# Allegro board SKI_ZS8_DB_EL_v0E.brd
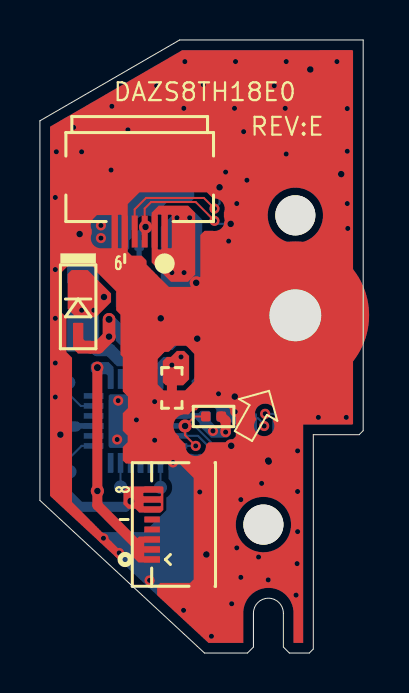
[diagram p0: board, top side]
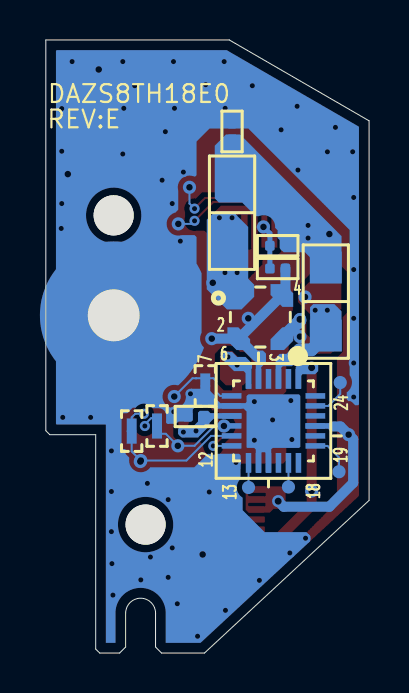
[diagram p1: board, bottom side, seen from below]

Outline 16.2 x 30.66 mm; copper layers: TOP, SGND, IN1, IN2, SVCC, IN3, SGND1, BOTTOM. Coordinates in mm from the lower left corner of the outline.
Outline path: 0,26.62 7,30.66 16.2,30.66 16.2,11.12 16,10.92 13.7,10.92 13.7,0.2 13.5,0 12.5,0 12.2,0.3 12.2,2 arc(11.45,2.75) 10.7,2 10.7,0.3 10.4,0 8.25,0 0,7.63 0,26.62

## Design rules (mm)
net group W20-T123B: nets +5V COM CS EL1 LX MAX14521E_1

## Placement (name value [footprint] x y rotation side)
C1  0.1u/25v_4  [CC0402]  8.7 11.83 0 bottom
C5  330p/50v_4  [CC0402]  4.58 20.37 180 bottom
C6  3300p/250v_1206  [CC1206]  2.17 17.58 90 bottom
CN1  196033-06021-3  [AF706L-A2G1T-6P-L-SMT]  5 23.88 180 top
CN2  50696-00801-001  [50696-0080M-V02-8P-L]  8.12 6.43 90 top
D4  bav21ws-7-f  [DSM]  1.91 17.32 270 top
HOLE1  *h-c291ic142d102p2  [H-C291IC142D102P2]  12.8 16.89 0 top
HOLE4  *h-c79d79n  [H-C79D79N]  12.8 21.89 0 top
HOLE5  *h-c79d79n  [H-C79D79N]  11.2 6.42 0 top
L10  mlps-3014pf-1r9111 /0.7a  [L3X3-1_4-4P]  5.45 16.8 180 bottom
NOREF  -  []  14.28 -45.03 0 top
NOREF#2  -  []  -39.05 -85.23 0 top
PC160  10u/25v_1206  [CC1206]  6.87 22.02 270 bottom
R20  *short_4  [SHORT0402]  10.63 11.35 270 bottom
R21  *short_4  [SHORT0402]  11.9 11.1 270 bottom
R24  20_4  [RC0402]  4.58 19.23 0 bottom
R25  *short_4  [SHORT0402]  8.21 13.35 90 bottom
R39  33k/f_4  [RC0402]  8.7 11.83 0 top
R40  *short_4  [SHORT0402]  6.61 13.26 270 top
R41  *0_4  [RC0402]  6.87 26.09 270 bottom
TP13  *pad  [TP2675]  6.04 8.28 180 bottom
TP15  *pad  [TP2675]  1.45 13.53 180 bottom
TP16  *pad  [TP2675]  1.51 9.07 180 bottom
TP17  *pad  [TP2675]  4.04 8.31 180 bottom
U1  max14521e  [QFN24-4X4-5-25P]  4.79 11.61 270 bottom

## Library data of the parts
C1 C5 = CC0402
C6 PC160 = CC1206
CN1 = AF706L-A2G1T-6P-L-SMT
CN2 = 50696-0080M-V02-8P-L
D4 = DSM
HOLE1 = H-C291IC142D102P2
HOLE4 HOLE5 = H-C79D79N
L10 = L3X3-1_4-4P
R20 R21 R25 R40 = SHORT0402
R24 R39 R41 = RC0402
TP13 TP15-TP17 = TP2675
U1 = QFN24-4X4-5-25P

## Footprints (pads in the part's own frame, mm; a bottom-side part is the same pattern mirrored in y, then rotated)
50696-0080M-V02-8P-L
  rect 0.305x0.787 smd: 1(-1.75,2.5) 2(-1.25,2.5) 3(-0.75,2.5) 4(-0.25,2.5) 5(0.25,2.5) 6(0.75,2.5) 7(1.25,2.5) 8(1.75,2.5)
  rect 0.406x0.787 smd: 9(-2.75,0) 10(2.75,0)
AF706L-A2G1T-6P-L-SMT
  rect 0.305x1.6 smd: 1(-1.25,2.8) 2(-0.75,2.8) 3(-0.25,2.8) 4(0.25,2.8) 5(0.75,2.8) 6(1.25,2.8)
  rect 1.803x1.397 smd: 7(-2.9,0) 8(2.9,0)
CC0402
  custom 0.12x0.12 smd: 1(0.39,0) 2(-0.39,0)
CC1206
  rect 1.6x1.6 smd: 1(1.702,0) 2(-1.702,0)
DSM
  rect 1.016x0.508 smd: 1(-1.3,0) 2(1.321,0)
H-C79D79N
  round 2.007 hole 2.007 unplated: (0,0)
H-C291IC142D102P2
  round 7.391 hole 2.591: 1(0,0)
L3X3-1_4-4P
  custom 0.285x0.285 smd: 1(-1.08,1.08) 2(-1.08,-1.08) 3(1.08,-1.08) 4(1.08,1.08)
QFN24-4X4-5-25P
  rect 0.991x0.279 smd: 1(-2.1,1.25) 2(-2.1,0.75) 3(-2.1,0.25) 4(-2.1,-0.25) 5(-2.1,-0.75) 6(-2.1,-1.25) 13(2.1,-1.25) 14(2.1,-0.75) 15(2.1,-0.25) 16(2.1,0.25) 17(2.1,0.75) 18(2.1,1.25)
  rect 0.279x0.991 smd: 7(-1.25,-2.1) 8(-0.75,-2.1) 9(-0.25,-2.1) 10(0.25,-2.1) 11(0.75,-2.1) 12(1.25,-2.1) 19(1.25,2.1) 20(0.75,2.1) 21(0.25,2.1) 22(-0.25,2.1) 23(-0.75,2.1) 24(-1.25,2.1)
  rect 2.591x2.591 smd: 25(0,0)
RC0402
  custom 0.12x0.12 smd: 1(0.39,0) 2(-0.39,0)
SHORT0402
  rect 0.648x0.5 smd: 1(-0.39,0) 2(0.39,0)
TP2675
  round 0.66 smd: 1(0,0)

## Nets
+5V: C1.2 CN1.1 CN1.2 L10.1 PC160.1 R39.1 U1.9
GND: C1.1 CN1.5 CN1.6 CN1.7 CN1.8 CN2.9 CN2.10 HOLE1.1 R25.1 R40.2 R41.2 U1.8 U1.14 U1.15 U1.25
PGND: C5.1 C6.1 PC160.2 R40.1 R41.1 U1.6
AUX: TP13.1 U1.13
COM: CN2.6 CN2.7 CN2.8 U1.21
CS: C6.2 D4.1 U1.3
EL1: CN2.1 CN2.2 CN2.3 U1.1
EL2: TP15.1 U1.23
EL3: TP16.1 U1.19
EL4: TP17.1 U1.17
EL_SCL: CN1.4 R21.1
EL_SDA: CN1.3 R20.1
KEYBOARD_SCL: R21.2 U1.11
KEYBOARD_SDA: R20.2 U1.10
LX: L10.2 L10.4 R24.2 U1.5
MAX14521E_1: D4.2 L10.3
RB: R39.2 U1.12
N17530158: C5.2 R24.1
N17530494: R25.2 U1.7

Pads without a net: CN2 4 5; U1 2 4 16 18 20 22 24

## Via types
v1: diameter 0.66, hole 0.33, TOP to BOTTOM, 19 vias
v2: diameter 0.61, hole 0.356, TOP to BOTTOM, 3 vias
v3: diameter 0.508, hole 0.254, TOP to BOTTOM, 76 vias

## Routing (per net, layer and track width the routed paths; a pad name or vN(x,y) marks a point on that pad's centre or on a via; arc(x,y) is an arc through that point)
+5V: length 0.9
  TOP w0.508: v3(9.31,11.05) 9.31,11.62 R39.1
  vias: v1(7.83,18.52) v3(6.61,19.02) v3(6.87,21.77) v3(7.22,19.02) v3(7.5,21.77) v3(8.67,11.11)
GND:
  vias: v1(6.06,16.74) v1(8.34,4.93) v1(11.47,9.58) v1(13.55,29.18) v1(15.1,23.95) v3(0.82,25.07) v3(0.77,22.78) v3(0.77,19.18) v3(0.77,16.74) v3(0.77,14.5) v3(0.77,12.8) v3(1.69,26.29) v3(2.09,25.07) v3(3.18,5.74) v3(3.61,27.34) v3(3.57,24.16) v3(3.92,12.62) v3(3.87,10.68) v3(3.97,5) v3(4.41,26.17) v3(4.84,11.66) v3(5.5,3.63) v3(5.75,12.57) v3(5.75,10.64) v3(5.85,28.37) v3(6.67,9.53) v3(7.21,27.24) v3(7.2,2.13) v3(7.26,29.58) v3(8.01,8.05) v3(8.19,28.42) v3(8.6,0.84) v3(8.95,12.96) v3(9.31,24.05) v3(9.46,20.6) v3(9.61,2.46) v3(9.8,29.58) v3(9.75,27.24) v3(9.79,12.07) v3(9.87,22.48) v3(9.87,5.26) v3(10.07,7.67) v3(10.07,3.78) v3(10.21,26.07) v3(10.37,23.65) v3(10.96,4.8) v3(11.11,8.48) v3(11.44,3.66) v3(11.74,28.37) v3(12.34,29.58) v3(12.29,27.24) v3(12.34,24.96) v3(12.84,2.9) v3(12.91,10.11) v3(12.91,8.08) v3(12.91,6.07) v3(12.89,4.47) v3(13.95,11.79) v3(14.88,29.58) v3(15.4,27.23) v3(15.4,25.1) v3(15.4,22.48) v3(15.43,21.23) v3(15.35,11.79)
PGND:
  vias: v1(1.99,20.95) v3(3.06,21.39) v3(3.06,20.75) v3(6.61,14.4) v3(7.07,14.81)
AUX: length 1.2
  BOTTOM w0.102: TP13.1 U1.13
COM: length 7.8
  BOTTOM w0.508: v2(4.56,7.59) 4.28,7.32 1.99,7.32 0.8,8.51 0.8,10.69 v1(1.03,10.92) 1.43,11.33 1.81,11.33
CS: length 2.2
  BOTTOM w0.635: 3.92,14.73 3.49,15.16 2.88,15.16 C6.2
  vias: v1(3.21,17.81) v3(2.09,17.15) v3(2.7,17.15)
EL1: length 9.8
  TOP w0.508: v2(2.88,14.27) v1(2.88,8.1) 2.88,7.39 4.91,5.36
EL2: length 2.1
  BOTTOM w0.102: U1.23 2.04,12.36 1.45,12.95 TP15.1
EL3: length 2.1
  BOTTOM w0.102: TP16.1 1.51,9.78 2.09,10.36 U1.19
EL4: length 1.2
  BOTTOM w0.102: TP17.1 U1.17
EL_SCL: length 19.3
  TOP w0.102: CN1.4 4.75,22.19 5.32,22.76 8.21,22.76 v3(8.75,22.23)
  IN1 w0.114: v3(11.29,11.96) 8.9,14.35 8.9,21.01 9.2,21.31 9.2,21.77 v3(8.75,22.23)
  BOTTOM w0.102: v3(11.29,11.96) 11.72,11.96 11.9,11.79 R21.1 ; v1(9,23.29) 9,22.48 v3(8.75,22.23)
EL_SDA: length 18.2
  TOP w0.102: v3(8.75,21.62) 7.81,22.56 5.57,22.56 5.25,22.23 CN1.3
  IN1 w0.114: v3(8.75,21.62) 8.65,21.51 8.65,13.94 v3(11.24,11.35)
  BOTTOM w0.102: v3(8.75,21.62) 8.9,21.46 v1(9.56,21.46) ; v3(11.24,11.35) 11.24,11.43 10.92,11.74 R20.1
KEYBOARD_SCL: length 6.3
  BOTTOM w0.102: R21.2 11.9,10.08 v1(11.44,9.63) 9.15,9.63 7.92,10.86 U1.11
KEYBOARD_SDA: length 4.4
  BOTTOM w0.102: U1.10 7.75,11.36 8.75,10.36 v1(9.59,10.36) 10.19,10.96 R20.2
LX: length 7.1
  BOTTOM w0.508: R24.2 4.19,18.06 L10.4 L10.2 ; 5.63,14.82 L10.2 ; L10.2 v1(7.88,15.72)
MAX14521E_1: length 3.3
  TOP w0.635: v2(3.46,16.69) v1(3.46,15.82) 2.93,15.29 2.55,15.29
  BOTTOM w0.635: v2(3.46,16.69) 3.46,16.63 L10.3
RB: length 3.4
  TOP w0.102: v3(7.81,10.36) 7.27,10.89 v1(7.27,11.35) 7.75,11.83 R39.2
  BOTTOM w0.102: v3(7.81,10.36) U1.12
N17530158: length 2.2
  BOTTOM w0.254: R24.1 C5.2 4.97,20.99 v1(5.29,21.31)
N17530494: length 3.9
  BOTTOM w0.102: v1(9.76,12.83) 8.85,13.74 8.67,13.74 8.67,13.74 R25.2 7.81,13.74 7.66,13.59 7.66,13.06 7.46,12.86 U1.7

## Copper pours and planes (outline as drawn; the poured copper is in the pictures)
+5V on TOP (solid shape): 7.78,22.02 7.78,18.92 7.43,18.57 6.56,18.57 5.6,19.53 5.6,21.9 5.9,21.9 5.9,20.22 5.94,20.18 6.06,20.18 6.1,20.22 6.1,21.88 6.4,21.88 6.4,20.28 6.44,20.24 6.57,20.24 6.61,20.28 6.61,21.88 6.56,21.92 6.45,21.92 6.4,21.88 6.1,21.88 6.1,21.89 6.06,21.93 5.94,21.93 5.9,21.9 5.6,21.9 5.6,22.02 5.95,22.38 7.43,22.38
+5V on BOTTOM (solid shape): 8.14,21.67 8.14,18.2 7.12,17.18 6.4,17.18 5.76,17.82 5.76,18.42 6.06,18.72 6.06,21.31 6.77,22.02 7.78,22.02
+5V on BOTTOM (solid shape): 8.57,12.02 8.57,11.57 8.82,11.33 9.44,11.33 9.57,11.2 9.57,10.95 9.39,10.77 8.57,10.77 8,11.35 8,11.5 7.78,11.72 6.4,11.72 6.4,11.72 6.4,11.99 6.4,12 7.95,12 8.07,12.12 8.47,12.12
+5V on SVCC (solid shape): 8.14,22.42 8.14,15.57 9.92,13.79 9.92,11.2 9.43,10.72 8.37,10.72 5.34,13.74 5.34,22.3 6.08,23.04 7.52,23.04
GND on TOP (solid shape): outline of 575 points within 0.51,0.51 15.69,30.15
GND on BOTTOM (solid shape): outline of 549 points within 0.51,0.51 15.69,30.15
GND on SGND (solid shape): outline of 392 points within 0.51,0.51 15.69,30.15
GND on IN1 (solid shape): outline of 1023 points within 0.51,0.51 15.69,30.15
GND on IN2 (solid shape): outline of 1080 points within 0.51,0.51 15.69,30.15
GND on SVCC (solid shape): outline of 407 points within 0.51,0.51 15.69,30.15
GND on IN3 (solid shape): outline of 1079 points within 0.51,0.51 15.69,30.15
GND on SGND1 (solid shape): outline of 370 points within 0.51,0.51 15.69,30.15
PGND on TOP (solid shape): 7.48,14.86 7.48,13.69 7.17,13.39 6.31,13.39 6.16,13.54 6.16,14.61 6.36,14.81 6.56,14.81 6.87,15.11 7.22,15.11
PGND on BOTTOM (solid shape): 7.38,14.91 7.38,14.71 6.77,14.1 6.28,14.1 6.18,14 6.18,13.23 6.17,13.21 5.91,13.21 5.9,13.22 5.9,14.2 5.87,14.24 5.87,14.48 6.19,14.81 6.61,14.81 6.87,15.06 7.22,15.06
PGND on BOTTOM (solid shape): 7.73,25.37 7.73,22.73 7.53,22.53 6.36,22.53 5.68,21.85 5.53,21.85 4.96,21.79 4.71,21.29 4.71,21.27 4.59,21.15 4.59,20.76 4.48,20.65 4.48,20.24 4.28,20.04 3.21,20.04 2.96,19.79 2.96,18.53 2.94,18.52 1.42,18.52 1.38,18.55 1.38,20.85 6.46,25.93 7.17,25.93
PGND on SGND1 (solid shape): 8.14,25.35 8.14,15.4 6,13.26 5.2,13.26 4.21,14.25 3.82,15.21 2.85,15.6 1.41,17.05 1.41,20.9 6.34,25.83 7.65,25.83
COM on TOP (solid shape): 6.19,8.29 6.19,7.16 6.05,7.02 4.97,7.02 4.79,7.21 4.41,7.21 4.18,7.44 4.18,7.5 5.2,7.5 5.2,7.36 6.01,7.33 6.06,7.38 6.01,7.52 5.23,7.52 5.2,7.5 4.18,7.5 4.18,7.98 5.18,7.98 5.18,7.87 5.23,7.83 6.01,7.83 6.06,7.88 6.06,7.98 6.01,8.02 5.22,8.02 5.18,7.98 4.18,7.98 4.18,8.1 4.41,8.33 6.15,8.33
CS on TOP (solid shape): 3.57,17.98 3.57,17.55 2.8,16.79 1.82,16.79 1.39,17.21 1.39,18.96 1.58,19.15 2.4,19.15
CS on BOTTOM (solid shape): 2.96,17.3 2.96,15.14 2.93,15.11 1.39,15.11 1.38,15.12 1.38,17.09 1.74,17.45 2.8,17.45
CS on BOTTOM (solid shape): 4.68,14.76 4.68,14.21 4.68,14.2 4.68,13.23 4.67,13.21 4.42,13.21 4.4,13.23 4.4,14.26 4.32,14.34 3.86,14.34 3.72,14.49 3.72,14.81 3.87,14.96 4.48,14.96
EL1 on TOP (solid shape): 6.01,5.52 5.23,5.52 5.23,5.33 6.01,5.33 6.01,5.02 5.23,5.02 5.23,4.83 6.01,4.83 6.01,4.52 4.95,4.52 4.66,4.81 4.66,5.52 4.97,5.83 6.01,5.83
EL1 on BOTTOM (solid shape): 3.68,14.31 3.68,13.22 3.67,13.21 3.41,13.21 3.4,13.22 3.4,13.87 3.33,13.94 2.7,13.94 2.55,14.1 2.55,14.43 2.67,14.55 3.44,14.55
MAX14521E_1 on TOP (solid shape): 2.17,16.48 2.17,15.7 2.25,15.62 2.56,15.62 2.73,15.45 2.73,15.13 2.58,14.97 1.91,14.97 1.66,15.22 1.66,16.48 1.69,16.51 2.14,16.51

Small or netless copper shapes (teardrops, artwork), in the pictures only: 2 on BOTTOM

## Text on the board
Ref Des/Silkscreen Bottom: DAZS8TH18E0 | REV:E
Ref Des/Silkscreen Top: DAZS8TH18E0 | REV:E
User.45: FIGURE | TYPE | Circle | SIZE | 10.0 | 14.0 | 102.0 | 79.0 | DRILL CHART: TOP to BOTTOM | ALL UNITS ARE IN MILS | PLATED | NON-PLATED | ROTATION | - | QTY | 76 | 3 | 1 | 2 | 82 | TOTAL HOLES:
